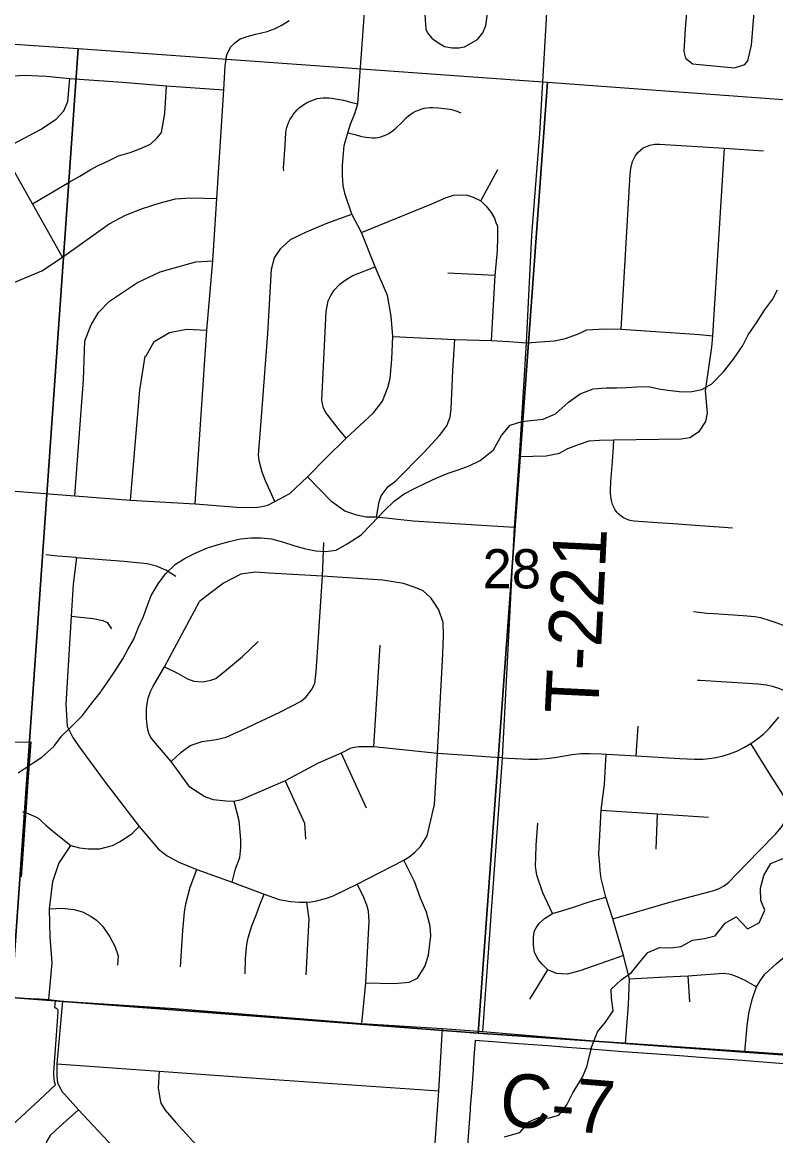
# Model space of a CAD drawing. Extents: x 0 to 34, y 0 to 22.
# Drawn here: x 4.196 to 5, y 16.043 to 17.23 of the extents above; entities that cross this region are included whole.
import ezdxf

# ---------------------------------------------------------------- set-up
doc = ezdxf.new("R2010")
doc.units = 0
for name, color, linetype in [('GM_X_Corporation', 7, 'Continuous'), ('GM_X_County_Road', 7, 'Continuous'), ('GM_X_County_Road_Text', 7, 'Continuous'), ('GM_X_Minor_River', 7, 'Continuous'), ('GM_X_Section_Text', 7, 'Continuous'), ('GM_X_Township_Road', 7, 'Continuous'), ('GM_X_Township_Road_Text', 7, 'Continuous')]:
    doc.layers.add(name, color=color, linetype=linetype)

msp = doc.modelspace()

# ---------------------------------------------------------------- linework, layer by layer
at = {"layer": 'GM_X_Corporation'}
for points in [[(3.7496, 17.2367), (4.2556, 17.2022), (4.1846, 16.1905), (3.6755, 16.2252)], [(4.7567, 17.1664), (4.6827, 16.1525), (4.1846, 16.1905), (4.2556, 17.2022)], [(5.2498, 17.1302), (5.1838, 16.1166), (5.1682, 16.119), (4.6827, 16.1525), (4.7567, 17.1664)], [(4.1846, 16.1905), (4.6827, 16.1525), (5.1682, 16.119), (5.1019, 15.1206), (4.1115, 15.1948)]]:
    msp.add_lwpolyline(points, close=True, dxfattribs=at)
for points in [[(4.1954, 16.3189), (4.1971, 16.3431), (4.1996, 16.3794), (4.2006, 16.3933), (4.2025, 16.4207), (4.2055, 16.4625), (4.1861, 16.4622)], [(4.1861, 16.0548), (4.2087, 16.0758), (4.2314, 16.0972), (4.2305, 16.1005), (4.23, 16.104), (4.2297, 16.1075), (4.2298, 16.111), (4.2327, 16.1504), (4.2345, 16.1752), (4.2344, 16.1759), (4.2343, 16.1765), (4.2341, 16.1771), (4.2337, 16.1777), (4.2333, 16.1782), (4.2328, 16.1786), (4.2322, 16.1789), (4.2316, 16.1791), (4.231, 16.1792), (4.2315, 16.1868), (4.1966, 16.1893), (4.1862, 16.1901)], [(5.0278, 16.1183), (4.9999, 16.1204), (4.9816, 16.1218), (4.9551, 16.1238), (4.9287, 16.1257), (4.8974, 16.1281), (4.8682, 16.1303), (4.8371, 16.1326), (4.8021, 16.1352), (4.7775, 16.1371), (4.7568, 16.1388), (4.736, 16.1404), (4.7207, 16.1415), (4.6981, 16.1432), (4.6794, 16.1446), (4.6787, 16.1352), (4.6781, 16.1273), (4.6767, 16.1084), (4.6753, 16.0895), (4.6741, 16.0733), (4.6739, 16.0706), (4.6725, 16.0517), (4.6712, 16.0328)]]:
    msp.add_lwpolyline(points, dxfattribs=at)
at = {"layer": 'GM_X_County_Road'}
msp.add_line((4.2198, 16.1886), (4.2246, 16.1884), dxfattribs=at)
for points in [[(4.196, 16.1897), (4.2141, 16.1889), (4.2198, 16.1886)], [(4.2246, 16.1884), (4.2391, 16.1866), (4.3591, 16.1786), (4.5586, 16.1626), (4.6445, 16.1573), (4.6875, 16.154), (4.8399, 16.1412), (4.9672, 16.1321), (5.2793, 16.1102), (5.4249, 16.0979), (5.4818, 16.0947), (5.5374, 16.0903), (5.5601, 16.0891), (5.5855, 16.0875), (5.6227, 16.0842), (5.6747, 16.0795), (5.8624, 16.0651), (5.8664, 16.0647)]]:
    msp.add_lwpolyline(points, dxfattribs=at)
at = {"layer": 'GM_X_Minor_River'}
for points in [[(4.9965, 16.9346), (5.0019, 16.9448)], [(4.1919, 16.4299), (4.2076, 16.4407), (4.2171, 16.4467), (4.2298, 16.4579), (4.2379, 16.4691), (4.2486, 16.4792), (4.2602, 16.4909), (4.269, 16.5025), (4.2787, 16.5149), (4.2864, 16.5254), (4.2945, 16.5378), (4.3034, 16.5514), (4.3088, 16.5615), (4.3151, 16.5725), (4.3202, 16.5853), (4.3256, 16.5966), (4.3292, 16.6076), (4.3335, 16.6189), (4.3412, 16.6313), (4.349, 16.6422), (4.3597, 16.6523), (4.37, 16.659), (4.3807, 16.6642), (4.3936, 16.6697), (4.4066, 16.6737), (4.4168, 16.6766), (4.429, 16.6794), (4.4403, 16.6804), (4.4509, 16.6806), (4.4619, 16.6794), (4.4747, 16.6758), (4.486, 16.6722), (4.4969, 16.669), (4.5094, 16.6666), (4.5196, 16.666), (4.531, 16.6674), (4.5428, 16.6741), (4.5577, 16.6837), (4.5685, 16.6946), (4.5827, 16.7096), (4.593, 16.7197), (4.6037, 16.7275), (4.614, 16.7327), (4.6255, 16.7386), (4.6384, 16.7445), (4.6506, 16.7493), (4.6612, 16.7529), (4.673, 16.7573), (4.6848, 16.7628), (4.699, 16.7744), (4.7076, 16.7895), (4.7168, 16.8007), (4.7293, 16.8047), (4.7388, 16.8057), (4.7521, 16.8071), (4.765, 16.8126), (4.7788, 16.8253), (4.7914, 16.8342), (4.8051, 16.8394), (4.8192, 16.8403), (4.8305, 16.8405), (4.8407, 16.8408), (4.8517, 16.8414), (4.8642, 16.842), (4.8752, 16.8395), (4.885, 16.8379), (4.9001, 16.8361), (4.9107, 16.8364), (4.9213, 16.8385), (4.932, 16.8448), (4.9443, 16.8575), (4.9551, 16.8711), (4.9651, 16.8857), (4.9706, 16.897), (4.9795, 16.9098), (4.988, 16.9234), (4.9965, 16.9346)], [(4.7105, 16.0417), (4.7269, 16.0464), (4.7373, 16.058), (4.7472, 16.0625), (4.7574, 16.0619), (4.7688, 16.0648), (4.7772, 16.0761), (4.7835, 16.0889), (4.7939, 16.1055), (4.799, 16.1175), (4.8015, 16.1285), (4.8039, 16.1383), (4.8098, 16.1538), (4.8186, 16.164), (4.8267, 16.176), (4.825, 16.1897), (4.8244, 16.1992), (4.8352, 16.2093), (4.8462, 16.2171), (4.8547, 16.2276), (4.8636, 16.2385), (4.8761, 16.2436), (4.8882, 16.2435), (4.8992, 16.2448), (4.9111, 16.2515), (4.924, 16.2532), (4.9353, 16.2561), (4.9461, 16.2696), (4.958, 16.2763), (4.9699, 16.2636), (4.9825, 16.2699), (4.9883, 16.2834), (4.9843, 16.2937), (4.9838, 16.307), (4.9874, 16.3206), (4.9947, 16.3331), (5.0088, 16.339)]]:
    msp.add_lwpolyline(points, dxfattribs=at)
at = {"layer": 'GM_X_Township_Road'}
for p, q in [((4.6855, 17.04), (4.7036, 17.0732)), ((4.7002, 16.9603), (4.6501, 16.9628)), ((4.7154, 16.8897), (4.7343, 16.8884)), ((4.7214, 16.6916), (4.6919, 16.6934)), ((4.5712, 16.4575), (4.5779, 16.5661)), ((4.8511, 16.4479), (4.8533, 16.4796)), ((4.5364, 16.4509), (4.563, 16.3927)), ((4.8725, 16.3485), (4.874, 16.3863)), ((4.9083, 16.1857), (4.9067, 16.2136))]:
    msp.add_line(p, q, dxfattribs=at)
for points in [[(4.6875, 16.154), (4.7077, 16.4355), (4.7084, 16.446), (4.7214, 16.6916), (4.7267, 16.7674), (4.7343, 16.8884), (4.74, 17.0033), (4.7482, 17.1116), (4.7591, 17.2956), (4.7641, 17.3741), (4.7656, 17.4048), (4.7746, 17.4681), (4.7809, 17.5683), (4.7839, 17.6088), (4.786, 17.6509), (4.7861, 17.6586), (4.7854, 17.6687)], [(4.9243, 17.3447), (4.9104, 17.3331), (4.8995, 17.3232), (4.8952, 17.3159), (4.8924, 17.3106), (4.8911, 17.3048), (4.8902, 17.2998), (4.8897, 17.2929), (4.8927, 17.2818), (4.9014, 17.2585), (4.9035, 17.2536), (4.9047, 17.2399), (4.9036, 17.2237), (4.9021, 17.1991), (4.9039, 17.1921), (4.9116, 17.1859), (4.9153, 17.1855), (4.9561, 17.1818), (4.9671, 17.1851), (4.9704, 17.1892), (4.9744, 17.2057), (4.9843, 17.3279)], [(4.5003, 16.7454), (4.5199, 16.7654), (4.5417, 16.7869), (4.5708, 16.8138), (4.5805, 16.8264), (4.5862, 16.8409), (4.5887, 16.8503), (4.5906, 16.8711), (4.5915, 16.8951), (4.5897, 16.917), (4.5858, 16.9388), (4.5725, 16.9696), (4.5581, 17.006), (4.5476, 17.0255), (4.5405, 17.0467), (4.5386, 17.0558), (4.5377, 17.0672), (4.5377, 17.0777), (4.5384, 17.0862), (4.5396, 17.0988), (4.5436, 17.1123), (4.5464, 17.1214), (4.551, 17.1329), (4.5542, 17.1432), (4.5664, 17.3093)], [(4.6295, 17.3043), (4.6282, 17.2863), (4.6264, 17.2594), (4.6255, 17.2389), (4.6268, 17.2229), (4.6286, 17.2191), (4.6331, 17.2133), (4.6386, 17.2093), (4.6468, 17.2044), (4.6548, 17.2031), (4.6619, 17.2029), (4.6679, 17.2042), (4.6737, 17.2071), (4.6819, 17.2118), (4.6875, 17.2191), (4.6908, 17.2267), (4.6928, 17.2422), (4.6942, 17.264), (4.6959, 17.2998)], [(4.3807, 16.7166), (4.393, 16.9021), (4.3996, 16.9758), (4.4038, 17.0423), (4.4113, 17.1583), (4.4126, 17.1837), (4.4144, 17.1954), (4.4184, 17.2035), (4.423, 17.2083), (4.4286, 17.2127), (4.436, 17.2149), (4.4454, 17.2175), (4.4573, 17.2205), (4.4652, 17.2231), (4.4723, 17.2269), (4.481, 17.232)], [(4.0976, 17.0892), (4.1017, 17.092), (4.1288, 17.1124), (4.1363, 17.1219), (4.1442, 17.1377), (4.1525, 17.152), (4.1597, 17.1595), (4.1699, 17.1666), (4.183, 17.1726), (4.1976, 17.1738), (4.2218, 17.1726), (4.2467, 17.1702), (4.3029, 17.1662), (4.35, 17.1623), (4.4113, 17.1583)], [(4.1747, 17.0942), (4.2154, 17.116), (4.2321, 17.127), (4.2404, 17.1358), (4.2447, 17.1456), (4.2467, 17.1702)], [(4.207, 17.0366), (4.2462, 17.0599), (4.2576, 17.0663), (4.2686, 17.073), (4.277, 17.0776), (4.2873, 17.0823), (4.2987, 17.0877), (4.3114, 17.0914), (4.3215, 17.0954), (4.3328, 17.1004), (4.3402, 17.1071), (4.3446, 17.1128), (4.3482, 17.1329), (4.35, 17.1623)], [(4.4753, 17.0719), (4.475, 17.0747), (4.4755, 17.084), (4.4766, 17.0996), (4.4774, 17.112), (4.4778, 17.1151), (4.4785, 17.1181), (4.4795, 17.1211), (4.4806, 17.124), (4.482, 17.1268), (4.4836, 17.1295), (4.4853, 17.132), (4.4873, 17.1345), (4.4894, 17.1368), (4.4917, 17.1389), (4.4941, 17.1409), (4.4966, 17.1427), (4.4993, 17.1443), (4.5021, 17.1457), (4.505, 17.1469), (4.5079, 17.1479), (4.5109, 17.1488), (4.514, 17.1493), (4.5171, 17.1496), (4.5202, 17.1497), (4.5233, 17.1495), (4.5264, 17.1492), (4.5326, 17.1483), (4.5387, 17.147), (4.5478, 17.1448), (4.5542, 17.1432)], [(4.5436, 17.1123), (4.551, 17.1104), (4.5571, 17.1088), (4.5601, 17.1081), (4.5632, 17.1076), (4.5663, 17.1072), (4.5694, 17.107), (4.5725, 17.107), (4.5756, 17.1074), (4.5787, 17.108), (4.5816, 17.109), (4.5845, 17.1102), (4.5873, 17.1116), (4.5899, 17.1133), (4.5924, 17.1151), (4.5948, 17.1172), (4.6014, 17.1238), (4.6058, 17.1282), (4.6081, 17.1303), (4.6106, 17.1322), (4.6132, 17.1339), (4.6159, 17.1354), (4.6188, 17.1366), (4.6218, 17.1377), (4.6248, 17.1385), (4.6278, 17.139), (4.6309, 17.1393), (4.6341, 17.1394), (4.6403, 17.139), (4.6496, 17.138), (4.6527, 17.1375), (4.6557, 17.1368), (4.6587, 17.1359), (4.6616, 17.1348), (4.664, 17.1336)], [(4.2389, 16.9798), (4.207, 17.0366), (4.1747, 17.0942), (4.168, 17.1037), (4.1593, 17.1112), (4.1506, 17.1171), (4.1363, 17.1219)], [(4.7267, 16.7674), (4.755, 16.7681), (4.7692, 16.7709), (4.7783, 16.7756), (4.7897, 16.78), (4.801, 16.7841), (4.8121, 16.7846), (4.8272, 16.785), (4.8992, 16.7859), (4.9083, 16.7875), (4.9188, 16.7941), (4.9255, 16.8045), (4.9272, 16.8136), (4.9253, 16.8371), (4.9289, 16.8643), (4.9318, 16.8838), (4.9328, 16.8958), (4.9455, 17.0961)], [(4.8501, 17.0874), (4.8528, 17.0912), (4.8587, 17.0962), (4.8659, 17.0992), (4.8711, 17.1001), (4.8761, 17.1003), (4.9455, 17.0961), (4.9871, 17.0932)], [(4.8351, 16.903), (4.8449, 17.068), (4.8456, 17.0742), (4.8474, 17.0817), (4.8501, 17.0874)], [(4.0081, 16.876), (4.0146, 16.8763), (4.0203, 16.8777), (4.0283, 16.8808), (4.0362, 16.8852), (4.0454, 16.8929), (4.0562, 16.9037), (4.0661, 16.9102), (4.075, 16.9146), (4.0897, 16.9184), (4.1053, 16.9225), (4.1183, 16.9227), (4.134, 16.9283), (4.1796, 16.9495), (4.2169, 16.9653), (4.2389, 16.9798), (4.289, 17.0154), (4.3061, 17.0245), (4.3243, 17.0316), (4.3421, 17.0372), (4.3595, 17.0419), (4.3757, 17.0431), (4.4038, 17.0423)], [(4.5581, 17.006), (4.6333, 17.0368), (4.6476, 17.043), (4.6561, 17.0457), (4.6622, 17.0464), (4.6707, 17.0457), (4.6771, 17.0437), (4.6855, 17.04), (4.691, 17.0343), (4.6965, 17.0275), (4.7001, 17.0213), (4.7015, 17.0169), (4.7033, 17.0128), (4.7033, 17.0014), (4.7029, 16.987), (4.7002, 16.9603), (4.6964, 16.891)], [(4.4655, 16.7194), (4.4556, 16.7414), (4.452, 16.7506), (4.4492, 16.7613), (4.4481, 16.7688), (4.4523, 16.8234), (4.4581, 16.8984), (4.4621, 16.9671), (4.4652, 16.979), (4.4721, 16.9891), (4.4822, 16.9986), (4.5002, 17.0073), (4.522, 17.0165), (4.5476, 17.0255)], [(4.2522, 16.7253), (4.2613, 16.8491), (4.2628, 16.8905), (4.2695, 16.9077), (4.2775, 16.9207), (4.2891, 16.9329), (4.3189, 16.9526), (4.3431, 16.9642), (4.3597, 16.9687), (4.3814, 16.9748), (4.3996, 16.9758)], [(4.5417, 16.7869), (4.5333, 16.7971), (4.52, 16.8143), (4.5177, 16.8189), (4.5159, 16.8269), (4.5204, 16.9219), (4.5225, 16.9332), (4.5253, 16.9388), (4.5289, 16.9447), (4.5348, 16.9509), (4.5407, 16.9552), (4.5489, 16.9603), (4.5725, 16.9696)], [(4.3115, 16.7207), (4.3214, 16.8381), (4.3274, 16.8743), (4.3283, 16.8744), (4.337, 16.89), (4.3532, 16.8995), (4.3713, 16.9031), (4.393, 16.9021)], [(4.5915, 16.8951), (4.6577, 16.8919), (4.6964, 16.891), (4.7154, 16.8897)], [(4.7343, 16.8884), (4.7638, 16.8907), (4.7758, 16.8932), (4.7884, 16.8976), (4.7985, 16.9023), (4.8179, 16.9033), (4.8351, 16.903), (4.9188, 16.8973), (4.9328, 16.8958)], [(4.5741, 16.7025), (4.577, 16.7189), (4.5792, 16.7254), (4.5813, 16.728), (4.5864, 16.7352), (4.5948, 16.7414), (4.625, 16.772), (4.6413, 16.7895), (4.649, 16.8), (4.6526, 16.809), (4.6536, 16.8182), (4.6555, 16.8591), (4.6577, 16.8919)], [(4.9541, 16.6908), (4.9448, 16.6914), (4.914, 16.6937), (4.8955, 16.695), (4.8739, 16.6964), (4.8585, 16.6975), (4.8492, 16.6983), (4.8462, 16.6988), (4.8432, 16.6995), (4.8403, 16.7006), (4.8376, 16.702), (4.835, 16.7037), (4.8326, 16.7057), (4.8305, 16.7079), (4.8287, 16.7104), (4.8272, 16.7131), (4.826, 16.716), (4.8251, 16.7189), (4.8244, 16.722), (4.824, 16.725), (4.8238, 16.7281), (4.8238, 16.7312), (4.8242, 16.7405), (4.826, 16.762), (4.8268, 16.7775), (4.8272, 16.785)], [(4.421, 16.7134), (4.4251, 16.7131), (4.4453, 16.7127), (4.4517, 16.7138), (4.4581, 16.7155), (4.4655, 16.7194), (4.4815, 16.7276), (4.5003, 16.7454)], [(4.6919, 16.6934), (4.6133, 16.6981), (4.5741, 16.7025), (4.5632, 16.7025), (4.553, 16.7047), (4.5403, 16.709), (4.5264, 16.7189), (4.5003, 16.7454)], [(4.0562, 16.6908), (4.0838, 16.7029), (4.1085, 16.7164), (4.1332, 16.7277), (4.145, 16.732), (4.1645, 16.7324), (4.1884, 16.7303), (4.2522, 16.7253), (4.3115, 16.7207), (4.3807, 16.7166), (4.421, 16.7134)], [(4.3549, 16.4422), (4.3658, 16.4519), (4.3754, 16.4591), (4.3882, 16.4635), (4.403, 16.4655), (4.4138, 16.4679), (4.4364, 16.4783), (4.4716, 16.495), (4.4938, 16.5064), (4.499, 16.5109), (4.5049, 16.5183), (4.5083, 16.5253), (4.5097, 16.5376), (4.5123, 16.5746), (4.5164, 16.6398), (4.5179, 16.6754)], [(4.36, 16.6394), (4.3492, 16.6461), (4.3393, 16.6502), (4.3295, 16.6528), (4.3046, 16.6551), (4.2541, 16.6593), (4.2534, 16.6594), (4.2341, 16.6611), (4.2211, 16.6624)], [(4.2541, 16.6593), (4.2503, 16.631), (4.2484, 16.5971), (4.2427, 16.5031), (4.2441, 16.4796), (4.2499, 16.4677), (4.2562, 16.4589), (4.2835, 16.4213), (4.3208, 16.3726), (4.3416, 16.3485), (4.3508, 16.3414), (4.3632, 16.3348), (4.3822, 16.3267), (4.4199, 16.3135), (4.4541, 16.3007), (4.4701, 16.2948), (4.4824, 16.2926), (4.4918, 16.2919), (4.4997, 16.2921), (4.5043, 16.2925), (4.5101, 16.2936), (4.5195, 16.296), (4.528, 16.2989), (4.5534, 16.3112), (4.6031, 16.3369), (4.6086, 16.3401), (4.615, 16.3453), (4.621, 16.3513), (4.6281, 16.3629), (4.6359, 16.3961), (4.6393, 16.4504), (4.6447, 16.5568), (4.6456, 16.5767), (4.6452, 16.5902), (4.6405, 16.6036), (4.6354, 16.6119), (4.6322, 16.6166), (4.6239, 16.624), (4.6155, 16.6277), (4.603, 16.6318), (4.5808, 16.6355), (4.5164, 16.6398), (4.4594, 16.6428), (4.4446, 16.6439), (4.4294, 16.6416), (4.4109, 16.632), (4.3964, 16.6212), (4.3852, 16.6127)], [(4.7084, 16.446), (4.6955, 16.4466), (4.6711, 16.4485), (4.6393, 16.4504), (4.5712, 16.4575), (4.5553, 16.4575), (4.5468, 16.4564), (4.5364, 16.4509), (4.512, 16.4401), (4.4767, 16.4214), (4.4295, 16.4013), (4.4223, 16.3993), (4.4134, 16.3997), (4.4002, 16.4013), (4.391, 16.4042), (4.375, 16.4146), (4.3549, 16.4422), (4.3345, 16.4663), (4.3328, 16.4683), (4.3313, 16.4723), (4.33, 16.4762), (4.3294, 16.4806), (4.3286, 16.4878), (4.3285, 16.4977), (4.3293, 16.5039), (4.3303, 16.5097), (4.3329, 16.5168), (4.3356, 16.5223), (4.348, 16.5429), (4.3852, 16.6127)], [(4.9124, 16.6019), (4.9266, 16.6002), (4.9342, 16.5998), (4.9654, 16.5977), (4.9778, 16.5968), (4.9838, 16.5955), (4.9926, 16.5928), (5.0014, 16.5897), (5.0136, 16.5851), (5.0316, 16.5783)], [(4.2484, 16.5971), (4.2718, 16.5946), (4.2822, 16.5923), (4.2866, 16.5902), (4.2913, 16.5834)], [(4.348, 16.5429), (4.3625, 16.536), (4.3724, 16.5303), (4.3791, 16.5276), (4.3886, 16.527), (4.3973, 16.5286), (4.4026, 16.5306), (4.4141, 16.5396), (4.4311, 16.5538), (4.4477, 16.5701)], [(4.9165, 16.5288), (4.9196, 16.5288), (4.9534, 16.5266), (4.981, 16.5247), (4.9902, 16.5237), (4.9962, 16.5225), (5.0021, 16.5207), (5.017, 16.5149)], [(4.7084, 16.446), (4.715, 16.4457), (4.7367, 16.4445), (4.746, 16.4445), (4.7552, 16.4452), (4.7644, 16.4464), (4.7828, 16.4494), (4.7922, 16.4504), (4.8015, 16.4507), (4.814, 16.4503), (4.8192, 16.45), (4.8389, 16.4486), (4.8511, 16.4479), (4.8979, 16.4451), (4.9134, 16.4444), (4.9226, 16.4446), (4.9318, 16.4455), (4.9379, 16.4466), (4.9439, 16.448), (4.9497, 16.4498), (4.9584, 16.4532), (4.9667, 16.4573), (4.9734, 16.4613), (4.9797, 16.4655), (4.9869, 16.4712), (4.9936, 16.4776), (5.0035, 16.4894)], [(4.8263, 16.2741), (4.8871, 16.2919), (4.9339, 16.3044), (4.9397, 16.3065), (4.9452, 16.3093), (4.9501, 16.3132), (4.9587, 16.3221), (4.9825, 16.3466), (4.9998, 16.3644), (5.0059, 16.3715), (5.0091, 16.3768), (5.0111, 16.3826), (5.0119, 16.3888), (5.0118, 16.395), (5.0113, 16.398), (5.0105, 16.401), (5.0093, 16.4039), (5.0063, 16.4093), (4.9946, 16.4276), (4.9734, 16.4613)], [(4.8399, 16.1412), (4.843, 16.1826), (4.8442, 16.2104), (4.8378, 16.2352), (4.8263, 16.2741), (4.8188, 16.2974), (4.8138, 16.3172), (4.8129, 16.3259), (4.8124, 16.3318), (4.8113, 16.3431), (4.8138, 16.3903), (4.8175, 16.4177), (4.8192, 16.45)], [(4.4767, 16.4214), (4.4974, 16.3763), (4.4982, 16.3593)], [(4.4199, 16.3135), (4.4238, 16.3277), (4.4282, 16.3397), (4.4294, 16.3505), (4.4294, 16.359), (4.4274, 16.3789), (4.4223, 16.3993)], [(4.1962, 16.3882), (4.2025, 16.3867), (4.2127, 16.3818), (4.2211, 16.3743), (4.2305, 16.3662), (4.248, 16.3526), (4.2572, 16.3498), (4.2669, 16.3488), (4.279, 16.349), (4.2924, 16.3524), (4.2997, 16.3563), (4.3131, 16.3649), (4.3208, 16.3726)], [(4.8138, 16.3903), (4.874, 16.3863), (4.9285, 16.3826)], [(4.7618, 16.28), (4.7517, 16.3019), (4.7453, 16.321), (4.7438, 16.3305), (4.744, 16.3396), (4.7445, 16.3529), (4.7463, 16.3762)], [(4.2246, 16.1884), (4.2281, 16.2272), (4.2259, 16.2552), (4.2251, 16.2848), (4.2287, 16.314), (4.235, 16.3333), (4.248, 16.3526)], [(4.5627, 16.2059), (4.5931, 16.2054), (4.6088, 16.2066), (4.6179, 16.2111), (4.6258, 16.2235), (4.6297, 16.2356), (4.632, 16.2563), (4.6315, 16.2665), (4.6276, 16.2813), (4.6212, 16.2964), (4.6146, 16.3142), (4.6031, 16.3369)], [(4.3648, 16.2231), (4.3674, 16.2619), (4.3691, 16.2812), (4.3705, 16.2903), (4.3752, 16.3079), (4.3822, 16.3267)], [(4.4339, 16.2157), (4.4343, 16.2318), (4.4358, 16.2468), (4.4373, 16.2539), (4.4409, 16.2668), (4.4462, 16.2792), (4.4495, 16.2892), (4.4541, 16.3007)], [(4.5586, 16.1626), (4.5627, 16.2059), (4.5663, 16.2713), (4.5656, 16.2825), (4.5638, 16.2888), (4.5598, 16.2987), (4.5534, 16.3112)], [(4.4991, 16.2146), (4.5024, 16.2739), (4.4997, 16.2921)], [(4.8378, 16.2352), (4.8195, 16.2288), (4.7912, 16.2188), (4.7776, 16.2154), (4.7663, 16.2159), (4.7568, 16.2199), (4.7507, 16.2258), (4.7465, 16.2308), (4.7427, 16.2385), (4.7415, 16.2463), (4.7415, 16.2555), (4.7427, 16.2614), (4.7444, 16.2647), (4.7477, 16.2692), (4.7535, 16.2748), (4.7618, 16.28), (4.7729, 16.2833), (4.7842, 16.2868), (4.8011, 16.2923), (4.8188, 16.2974)], [(4.9672, 16.1321), (4.9697, 16.1604), (4.9717, 16.1755), (4.9752, 16.1892), (4.9797, 16.2017), (4.9833, 16.2083), (4.9884, 16.2154), (5.001, 16.2266), (5.0184, 16.2412), (5.025, 16.2453), (5.0342, 16.2504), (5.0654, 16.2695), (5.0755, 16.2762), (5.0824, 16.2823), (5.0933, 16.2908)], [(4.2251, 16.2848), (4.2386, 16.2855), (4.2513, 16.2842), (4.2603, 16.2818), (4.2697, 16.2769), (4.2752, 16.273), (4.282, 16.2662), (4.2897, 16.2552), (4.2948, 16.2453), (4.2983, 16.2348), (4.2977, 16.2249)], [(4.7378, 16.1886), (4.7469, 16.2037), (4.7568, 16.2199)], [(4.8442, 16.2104), (4.8823, 16.2124), (4.9067, 16.2136), (4.9441, 16.2163), (4.9502, 16.2156), (4.9529, 16.215), (4.9587, 16.2129), (4.9679, 16.2085), (4.9797, 16.2017)], [(4.2391, 16.1866), (4.2331, 16.1195), (4.2329, 16.106), (4.2338, 16.0996), (4.238, 16.0907), (4.256, 16.0706), (4.2823, 16.0425), (4.3987, 15.9187)], [(4.6361, 16.0255), (4.6405, 16.0907), (4.6445, 16.1573)], [(4.2331, 16.1195), (4.3421, 16.1117), (4.4653, 16.1029), (4.6405, 16.0907)], [(4.3421, 16.1117), (4.3411, 16.0939), (4.3429, 16.0829), (4.3441, 16.0777), (4.3485, 16.0701), (4.3598, 16.057), (4.3781, 16.0373), (4.3897, 16.026), (4.3978, 16.0207), (4.4075, 16.0166), (4.42, 16.0134), (4.4314, 16.0126), (4.4443, 16.0146), (4.4556, 16.0175), (4.4702, 16.0215), (4.4856, 16.0264), (4.4997, 16.0312), (4.5103, 16.0324), (4.5228, 16.034), (4.5458, 16.0332), (4.5726, 16.0308), (4.6017, 16.0288), (4.6361, 16.0255)], [(4.256, 16.0706), (4.2366, 16.0531), (4.226, 16.0432), (4.2213, 16.0356)]]:
    msp.add_lwpolyline(points, dxfattribs=at)

# ---------------------------------------------------------------- texts
at = {"layer": 'GM_X_County_Road_Text'}
msp.add_text('C-7', height=0.05682, rotation=355.4251, dxfattribs=at).set_placement((4.704, 16.054))
at = {"layer": 'GM_X_Section_Text'}
msp.add_text('28', height=0.04186, rotation=0, dxfattribs=at).set_placement((4.6873, 16.6266))
at = {"layer": 'GM_X_Township_Road_Text'}
msp.add_text('T-221', height=0.05682, rotation=87.1941, dxfattribs=at).set_placement((4.8104, 16.4917))

doc.saveas('drawing.dxf')
